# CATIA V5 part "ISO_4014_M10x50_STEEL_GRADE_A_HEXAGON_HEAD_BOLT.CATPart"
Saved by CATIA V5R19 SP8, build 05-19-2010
Part number: ISO 4014 BOLT M10x50 STEEL GRADE A HEXAGON HEAD
Nomenclature: 28
Publications: "Mating Face", "Axis"
Bounding box of the stored display mesh (mm): x -50 to 6.58, y -8 to 8, z -9.238 to 9.238
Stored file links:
  C:\Users\rphgr\Desktop\0_Tapis_TC520B_vitesse\ISO_4014_M10x50_STEEL_GRADE_A_HEXAGON_HEAD_BOLT.CATPart
  D:\Programmes\DassaultSysteme\win_b64\startup\components\MechanicalStandardParts\EN_Standards\Design_Tables\EN_ISO_4014_GRADES_A_B_HEXAGON_HEAD_BOLT.txt
  C:\Program Files\Dassault Systemes\B19\win_b64\startup\components\MechanicalStandardParts\ISO_Standards\Design_Tables\ISO_4014_GRADES_A_B_HEXAGON_HEAD_BOLT.txt
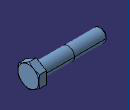
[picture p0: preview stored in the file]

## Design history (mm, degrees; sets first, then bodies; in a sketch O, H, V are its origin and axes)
Parameters
  d_dia = 10 mm
  l_length = 50 mm
  s_nom_across_flats = 16 mm
  k_max_head_depth = 6.58 mm
  dw_min = 14.63 mm
  r_min = 0.4 mm
  c_max = 0.6 mm
  p_pitch = 1.5 mm
  threading = 26 mm
Body1 "PartBody" (main body)
  Sketch1 on yz-plane, origin (0, 0, 0), H (0, 1, 0), V (0, 0, 1)
    circle A1 centre (0, 0) radius 7.315
    radius A1 = 7.315 {= dw_min /2}
  Pad1: profile Sketch1, direction (1, 0, 0), length 0.6 {= c_max}
  Sketch2 on face of Pad1, origin (0.6, 0, 0), H (0, 1, 0), V (0, 0, 1)
    point P1 (8, -4.6188)
    point P2 (8, 4.6188)
    point P3 (0, 9.2376)
    point P4 (-8, 4.6188)
    point P5 (-8, -4.6188)
    point P6 (0, -9.2376)
    point P7 (8, 0)
    line L1 (8, -4.6188) -> (8, 4.6188)
    line L2 (8, 4.6188) -> (0, 9.2376)
    line L3 (0, 9.2376) -> (-8, 4.6188)
    line L4 (-8, 4.6188) -> (-8, -4.6188)
    line L5 (-8, -4.6188) -> (0, -9.2376)
    line L6 (0, -9.2376) -> (8, -4.6188)
    construction line L7 (0, 0) -> (8, 0)
    construction circle A1 centre (0, 0) radius 9.2376
    construction arc A2 centre (-8, -4.6188) radius 9.2376 from (-8, 4.6188) to (0, -9.2376) cw
    construction arc A3 centre (8, 4.6188) radius 9.2376 from (0, 9.2376) to (8, -4.6188) ccw
    point P8 (-8, -4.6188)
    point P9 (8, 4.6188)
    distance L1 L4 = 16 {= s_nom_across_flats}
    horizontal: L7 H
    coincidence: A1 P1, A1 P2, A1 P3, A1 P4, A1 P5, A1 P6, A2 P4, A2 P6, A2 O, P8 P5, A3 P3, A3 P1, A3 O, P9 P2
    midpoint: P7 L1
  Pad2: profile Sketch2, direction (1, 0, 0), length 5.98 {= k_max_head_depth -c_max}
  Sketch3 on zx-plane, origin (0, 0, 0), H (-1, 0, 0), V (0, 0, 1)
    point P1 (-6.58, 7.9642)
    axis line L1 (-94.6904, 0) -> (76.7146, 0)
    reference intersected line E1 through (1000000, 0) direction (-1, 0) from xy-plane
    line L2 (-5.8448, 9.2376) -> (-6.58, 7.9642)
    line L3 (-5.8448, 9.2376) -> (-6.58, 9.2376)
    line L4 (-6.58, 9.2376) -> (-6.58, 7.9642)
    reference projected line E2 (-0.8, 9.2376) -> (-18.28, 9.2376) from edge [face of Pad2 | face of Pad2]
    distance P1 H = 7.9642 {= s_nom_across_flats /2.009}
    distance P1 V = 6.58 {= k_max_head_depth}
    angle L4 L2 = 30
    horizontal: L1 H, L3 H
    coincidence: L1 E1, L3 E2
    vertical: L4 V
  Groove1: profile Sketch3, axis Sketch3.L1, angle 360
  Sketch4 on face of Pad1, origin (0, 0, 0), H (0, -1, 0), V (0, 0, 1)
    circle A1 centre (0, 0) radius 5
    radius A1 = 5 {= d_dia /2}
  Pad3: profile Sketch4, direction (-1, 0, 0), length 24 {= l_length -threading}
  Sketch5 on face of Pad3, origin (-24, 0, 0), H (0, -1, 0), V (0, 0, 1)
    circle A1 centre (0, 0) radius 4.878
    radius A1 = 4.878 {= d_dia /2.05}
  Pad4: profile Sketch5, direction (-1, 0, 0), length 26 {= threading}
  Chamfer1: length 1.5 {= p_pitch}, angle 45, on face of Pad4
  Fillet1: radius 0.4 {= r_min}, on edge [face of Pad3 | face of Pad1]
  Thread1: diameter 9.7561 {= d_dia /1.025}, depth 26 {= threading}, pitch 1, on face of Pad4, from face of Pad4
